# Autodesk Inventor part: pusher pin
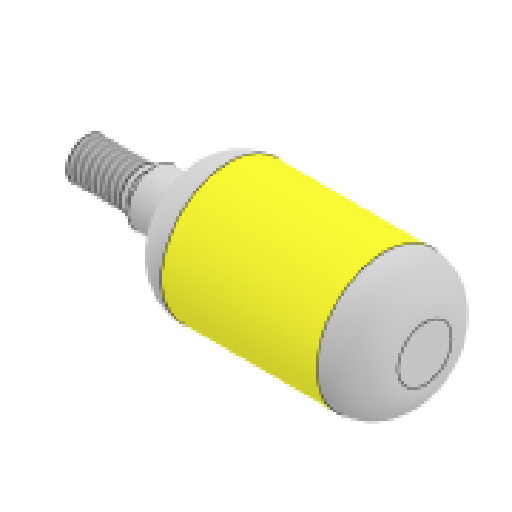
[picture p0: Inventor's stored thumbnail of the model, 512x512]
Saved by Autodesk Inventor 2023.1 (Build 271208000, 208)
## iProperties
Created: 2023-01
Part Number: pusher pin
Material: Generic
Document SubType Name: Modeling
Designer: Fabian
Density: 1 g/cm^3
Appearance: Default
Author: Fabian
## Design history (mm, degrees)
sketch "Sketch1"
  geometry: L1 (0, 0)-(25, 0); L2 (0, 0)-(0, 1.5); L3 (5, 1.5)-(5, 2); L4 (5, 2)-(7.5, 2); L5 (7.5, 2)-(7.5, 5); L6 (7.5, 5)-(25, 5); L7 (25, 5)-(25, 0); L8 (0, 1.5)-(4, 1.5); L9 (4, 1.5)-(4.25, 1.25); L10 (4.25, 1.25)-(4.75, 1.25); L11 (5, 1.5)-(5, 1.5); L12 (4.75, 1.25)-(5, 1.5); 2 further points
  constraints: 24 end point, 5 perpendicular, 2 horizontal, 2 point on line, 1 parallel, 1 vertical
  dimensions: "L" = 25 distance of L1.start L1.end; "d2" = 5 distance of L2.end L3.start; "d3" = 4 diameter of L4 L1; "d4" = 10 diameter of L6 L1; "d9" = 2.5 distance of L3.end L4.end; "d10" = 3 diameter of L8 L1; "d11" = 45 deg angle of L8 L9; "d13" = 1 distance from line of L3 L8.end; "d14" = 0.25 distance between parallel lines of L8 L10; "d15" = 0.25 distance of L10.end point (5, 1.25); "d16" = 0.25 distance of L11.start point (5, 1.25) (= d15)
revolve "Revolution1" sketch "Sketch1" stored, may be unused: angle "d5" = 90 deg
thread "Thread1" dims "d6" = 4, "d7" = 0
fillet "Fillet1" dims "d8" = 3
body "Solid1"
